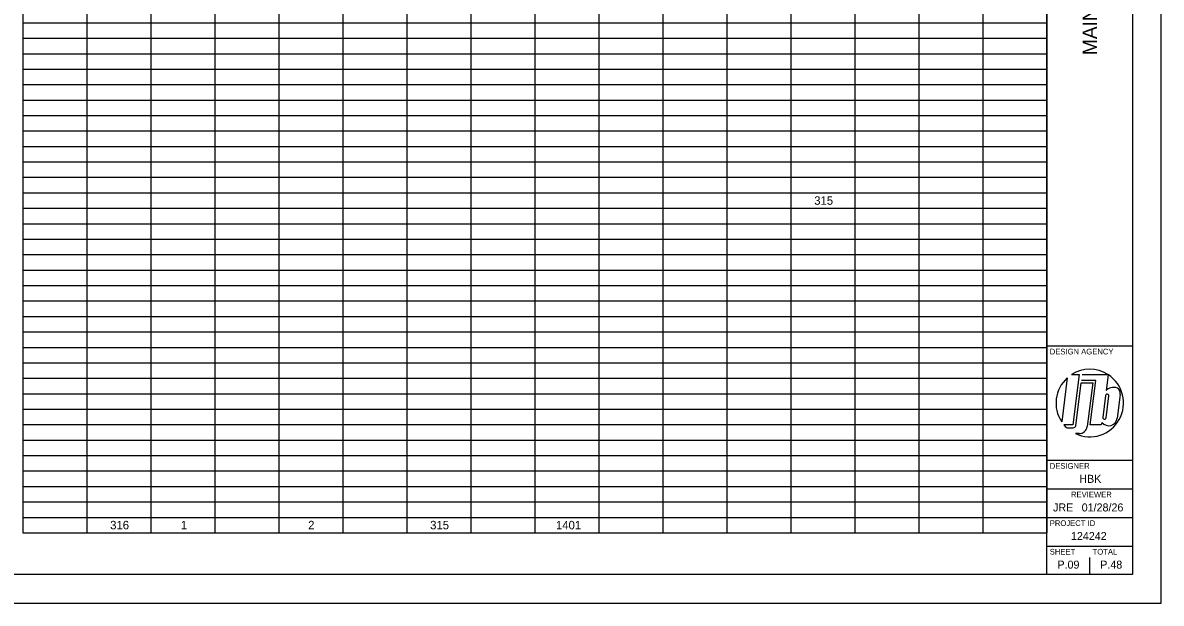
# Model space of a CAD drawing. Extents: x 0 to 34, y 0 to 22.
# Drawn here: x 14.09 to 34, y 0 to 10.15 of the extents above; entities that cross this region are included whole.
import ezdxf

# ---------------------------------------------------------------- set-up
doc = ezdxf.new("R2010")
doc.units = 0
for name, color, linetype in [('Default', 7, 'Continuous'), ('SH_Border', 7, 'Continuous'), ('SH_Cut_Line', 7, 'Continuous'), ('SH_Data', 7, 'Continuous')]:
    doc.layers.add(name, color=color, linetype=linetype)

msp = doc.modelspace()

# ---------------------------------------------------------------- linework, layer by layer
at = {"layer": 'Default'}
for p, q in [((14.086, 10.96), (14.086, 10.149)), ((15.206, 10.96), (15.206, 10.149)), ((16.325, 10.96), (16.325, 10.149)), ((17.445, 10.96), (17.445, 10.149)), ((18.565, 10.96), (18.565, 10.149)), ((19.684, 10.96), (19.684, 10.149)), ((20.804, 10.96), (20.804, 10.149)), ((21.923, 10.96), (21.923, 10.149)), ((23.043, 10.96), (23.043, 10.149)), ((24.163, 10.96), (24.163, 10.149)), ((25.282, 10.96), (25.282, 10.149)), ((26.402, 10.96), (26.402, 10.149)), ((27.522, 10.96), (27.522, 10.149)), ((28.641, 10.96), (28.641, 10.149)), ((29.761, 10.96), (29.761, 10.149)), ((30.88, 10.96), (30.88, 10.149)), ((32, 10.96), (32, 10.149)), ((14.086, 10.149), (15.206, 10.149)), ((14.086, 10.149), (14.086, 9.609)), ((15.206, 10.149), (16.325, 10.149)), ((15.206, 10.149), (15.206, 9.609)), ((16.325, 10.149), (24.163, 10.149)), ((16.325, 10.149), (16.325, 9.609)), ((17.445, 10.149), (17.445, 9.609)), ((18.565, 10.149), (18.565, 9.609)), ((19.684, 10.149), (19.684, 9.609)), ((20.804, 10.149), (20.804, 9.609)), ((21.923, 10.149), (21.923, 9.609)), ((23.043, 10.149), (23.043, 9.609)), ((24.163, 10.149), (25.282, 10.149)), ((24.163, 10.149), (24.163, 9.609)), ((25.282, 10.149), (27.522, 10.149)), ((25.282, 10.149), (25.282, 9.609)), ((26.402, 10.149), (26.402, 9.609)), ((27.522, 10.149), (30.88, 10.149)), ((27.522, 10.149), (27.522, 9.609)), ((28.641, 10.149), (28.641, 9.609)), ((29.761, 10.149), (29.761, 9.609)), ((30.88, 10.149), (32, 10.149)), ((30.88, 10.149), (30.88, 9.609)), ((32, 10.149), (32, 9.609)), ((14.086, 9.879), (15.206, 9.879)), ((15.206, 9.879), (16.325, 9.879)), ((16.325, 9.879), (24.163, 9.879)), ((24.163, 9.879), (25.282, 9.879)), ((25.282, 9.879), (27.522, 9.879)), ((27.522, 9.879), (30.88, 9.879)), ((30.88, 9.879), (32, 9.879)), ((14.086, 9.609), (15.206, 9.609)), ((14.086, 9.609), (14.086, 8.798)), ((15.206, 9.609), (16.325, 9.609)), ((15.206, 9.609), (15.206, 8.798)), ((16.325, 9.609), (24.163, 9.609)), ((16.325, 9.609), (16.325, 8.798)), ((17.445, 9.609), (17.445, 8.798)), ((18.565, 9.609), (18.565, 8.798)), ((19.684, 9.609), (19.684, 8.798)), ((20.804, 9.609), (20.804, 8.798)), ((21.923, 9.609), (21.923, 8.798)), ((23.043, 9.609), (23.043, 8.798)), ((24.163, 9.609), (25.282, 9.609)), ((24.163, 9.609), (24.163, 8.798)), ((25.282, 9.609), (27.522, 9.609)), ((25.282, 9.609), (25.282, 8.798)), ((26.402, 9.609), (26.402, 8.798)), ((27.522, 9.609), (30.88, 9.609)), ((27.522, 9.609), (27.522, 8.798)), ((28.641, 9.609), (28.641, 8.798)), ((29.761, 9.609), (29.761, 8.798)), ((30.88, 9.609), (32, 9.609)), ((30.88, 9.609), (30.88, 8.798)), ((32, 9.609), (32, 8.798)), ((14.086, 9.339), (15.206, 9.339)), ((15.206, 9.339), (16.325, 9.339)), ((16.325, 9.339), (24.163, 9.339)), ((24.163, 9.339), (25.282, 9.339)), ((25.282, 9.339), (27.522, 9.339)), ((27.522, 9.339), (30.88, 9.339)), ((30.88, 9.339), (32, 9.339)), ((14.086, 9.068), (15.206, 9.068)), ((15.206, 9.068), (16.325, 9.068)), ((16.325, 9.068), (24.163, 9.068)), ((24.163, 9.068), (25.282, 9.068)), ((25.282, 9.068), (27.522, 9.068)), ((27.522, 9.068), (30.88, 9.068)), ((30.88, 9.068), (32, 9.068)), ((14.086, 8.798), (15.206, 8.798)), ((14.086, 8.798), (14.086, 8.258)), ((15.206, 8.798), (16.325, 8.798)), ((15.206, 8.798), (15.206, 8.258)), ((16.325, 8.798), (24.163, 8.798)), ((16.325, 8.798), (16.325, 8.258)), ((17.445, 8.798), (17.445, 8.258)), ((18.565, 8.798), (18.565, 8.258)), ((19.684, 8.798), (19.684, 8.258)), ((20.804, 8.798), (20.804, 8.258)), ((21.923, 8.798), (21.923, 8.258)), ((23.043, 8.798), (23.043, 8.258)), ((24.163, 8.798), (25.282, 8.798)), ((24.163, 8.798), (24.163, 8.258)), ((25.282, 8.798), (27.522, 8.798)), ((25.282, 8.798), (25.282, 8.258)), ((26.402, 8.798), (26.402, 8.258)), ((27.522, 8.798), (30.88, 8.798)), ((27.522, 8.798), (27.522, 8.258)), ((28.641, 8.798), (28.641, 8.258)), ((29.761, 8.798), (29.761, 8.258)), ((30.88, 8.798), (32, 8.798)), ((30.88, 8.798), (30.88, 8.258)), ((32, 8.798), (32, 8.258)), ((14.086, 8.528), (15.206, 8.528)), ((15.206, 8.528), (16.325, 8.528)), ((16.325, 8.528), (24.163, 8.528)), ((24.163, 8.528), (25.282, 8.528)), ((25.282, 8.528), (27.522, 8.528)), ((27.522, 8.528), (30.88, 8.528)), ((30.88, 8.528), (32, 8.528)), ((14.086, 8.258), (15.206, 8.258)), ((14.086, 8.258), (14.086, 7.447)), ((15.206, 8.258), (16.325, 8.258)), ((15.206, 8.258), (15.206, 7.447)), ((16.325, 8.258), (24.163, 8.258)), ((16.325, 8.258), (16.325, 7.447)), ((17.445, 8.258), (17.445, 7.447)), ((18.565, 8.258), (18.565, 7.447)), ((19.684, 8.258), (19.684, 7.447)), ((20.804, 8.258), (20.804, 7.447)), ((21.923, 8.258), (21.923, 7.447)), ((23.043, 8.258), (23.043, 7.447)), ((24.163, 8.258), (25.282, 8.258)), ((24.163, 8.258), (24.163, 7.447)), ((25.282, 8.258), (27.522, 8.258)), ((25.282, 8.258), (25.282, 7.447)), ((26.402, 8.258), (26.402, 7.447)), ((27.522, 8.258), (30.88, 8.258)), ((27.522, 8.258), (27.522, 7.447)), ((28.641, 8.258), (28.641, 7.447)), ((29.761, 8.258), (29.761, 7.447)), ((30.88, 8.258), (32, 8.258)), ((30.88, 8.258), (30.88, 7.447)), ((32, 8.258), (32, 7.447)), ((14.086, 7.987), (15.206, 7.987)), ((15.206, 7.987), (16.325, 7.987)), ((16.325, 7.987), (24.163, 7.987)), ((24.163, 7.987), (25.282, 7.987)), ((25.282, 7.987), (27.522, 7.987)), ((27.522, 7.987), (30.88, 7.987)), ((30.88, 7.987), (32, 7.987)), ((14.086, 7.717), (15.206, 7.717)), ((15.206, 7.717), (16.325, 7.717)), ((16.325, 7.717), (24.163, 7.717)), ((24.163, 7.717), (25.282, 7.717)), ((25.282, 7.717), (27.522, 7.717)), ((27.522, 7.717), (30.88, 7.717)), ((30.88, 7.717), (32, 7.717)), ((14.086, 7.447), (15.206, 7.447)), ((14.086, 7.447), (14.086, 6.906)), ((15.206, 7.447), (16.325, 7.447)), ((15.206, 7.447), (15.206, 6.906)), ((16.325, 7.447), (24.163, 7.447)), ((16.325, 7.447), (16.325, 6.906)), ((17.445, 7.447), (17.445, 6.906)), ((18.565, 7.447), (18.565, 6.906)), ((19.684, 7.447), (19.684, 6.906)), ((20.804, 7.447), (20.804, 6.906)), ((21.923, 7.447), (21.923, 6.906)), ((23.043, 7.447), (23.043, 6.906)), ((24.163, 7.447), (25.282, 7.447)), ((24.163, 7.447), (24.163, 6.906)), ((25.282, 7.447), (27.522, 7.447)), ((25.282, 7.447), (25.282, 6.906)), ((26.402, 7.447), (26.402, 6.906)), ((27.522, 7.447), (30.88, 7.447)), ((27.522, 7.447), (27.522, 6.906)), ((28.641, 7.447), (28.641, 6.906)), ((29.761, 7.447), (29.761, 6.906)), ((30.88, 7.447), (32, 7.447)), ((30.88, 7.447), (30.88, 6.906)), ((32, 7.447), (32, 6.906)), ((14.086, 7.177), (15.206, 7.177)), ((15.206, 7.177), (16.325, 7.177)), ((16.325, 7.177), (24.163, 7.177)), ((24.163, 7.177), (25.282, 7.177)), ((25.282, 7.177), (27.522, 7.177)), ((27.522, 7.177), (30.88, 7.177)), ((30.88, 7.177), (32, 7.177)), ((14.086, 6.906), (15.206, 6.906)), ((14.086, 6.906), (14.086, 1.231)), ((15.206, 6.906), (16.325, 6.906)), ((15.206, 6.906), (15.206, 1.231)), ((16.325, 6.906), (24.163, 6.906)), ((16.325, 6.906), (16.325, 1.231)), ((17.445, 6.906), (17.445, 1.231)), ((18.565, 6.906), (18.565, 1.231)), ((19.684, 6.906), (19.684, 1.231)), ((20.804, 6.906), (20.804, 1.231)), ((21.923, 6.906), (21.923, 1.231)), ((23.043, 6.906), (23.043, 1.231)), ((24.163, 6.906), (25.282, 6.906)), ((24.163, 6.906), (24.163, 1.231)), ((25.282, 6.906), (27.522, 6.906)), ((25.282, 6.906), (25.282, 1.231)), ((26.402, 6.906), (26.402, 1.231)), ((27.522, 6.906), (30.88, 6.906)), ((27.522, 6.906), (27.522, 1.231)), ((28.641, 6.906), (28.641, 1.231)), ((29.761, 6.906), (29.761, 1.231)), ((30.88, 6.906), (32, 6.906)), ((30.88, 6.906), (30.88, 1.231)), ((32, 6.906), (32, 1.231)), ((14.086, 6.636), (15.206, 6.636)), ((15.206, 6.636), (16.325, 6.636)), ((16.325, 6.636), (24.163, 6.636)), ((24.163, 6.636), (25.282, 6.636)), ((25.282, 6.636), (27.522, 6.636)), ((27.522, 6.636), (30.88, 6.636)), ((30.88, 6.636), (32, 6.636)), ((14.086, 6.366), (15.206, 6.366)), ((15.206, 6.366), (16.325, 6.366)), ((16.325, 6.366), (24.163, 6.366)), ((24.163, 6.366), (25.282, 6.366)), ((25.282, 6.366), (27.522, 6.366)), ((27.522, 6.366), (30.88, 6.366)), ((30.88, 6.366), (32, 6.366)), ((14.086, 6.096), (15.206, 6.096)), ((15.206, 6.096), (16.325, 6.096)), ((16.325, 6.096), (24.163, 6.096)), ((24.163, 6.096), (25.282, 6.096)), ((25.282, 6.096), (27.522, 6.096)), ((27.522, 6.096), (30.88, 6.096)), ((30.88, 6.096), (32, 6.096)), ((14.086, 5.825), (15.206, 5.825)), ((15.206, 5.825), (16.325, 5.825)), ((16.325, 5.825), (24.163, 5.825)), ((24.163, 5.825), (25.282, 5.825)), ((25.282, 5.825), (27.522, 5.825)), ((27.522, 5.825), (30.88, 5.825)), ((30.88, 5.825), (32, 5.825)), ((14.086, 5.555), (15.206, 5.555)), ((15.206, 5.555), (16.325, 5.555)), ((16.325, 5.555), (24.163, 5.555)), ((24.163, 5.555), (25.282, 5.555)), ((25.282, 5.555), (27.522, 5.555)), ((27.522, 5.555), (30.88, 5.555)), ((30.88, 5.555), (32, 5.555)), ((14.086, 5.285), (15.206, 5.285)), ((15.206, 5.285), (16.325, 5.285)), ((16.325, 5.285), (24.163, 5.285)), ((24.163, 5.285), (25.282, 5.285)), ((25.282, 5.285), (27.522, 5.285)), ((27.522, 5.285), (30.88, 5.285)), ((30.88, 5.285), (32, 5.285)), ((14.086, 5.015), (15.206, 5.015)), ((15.206, 5.015), (16.325, 5.015)), ((16.325, 5.015), (24.163, 5.015)), ((24.163, 5.015), (25.282, 5.015)), ((25.282, 5.015), (27.522, 5.015)), ((27.522, 5.015), (30.88, 5.015)), ((30.88, 5.015), (32, 5.015)), ((14.086, 4.744), (15.206, 4.744)), ((15.206, 4.744), (16.325, 4.744)), ((16.325, 4.744), (24.163, 4.744)), ((24.163, 4.744), (25.282, 4.744)), ((25.282, 4.744), (27.522, 4.744)), ((27.522, 4.744), (30.88, 4.744)), ((30.88, 4.744), (32, 4.744)), ((14.086, 4.474), (15.206, 4.474)), ((15.206, 4.474), (16.325, 4.474)), ((16.325, 4.474), (24.163, 4.474)), ((24.163, 4.474), (25.282, 4.474)), ((25.282, 4.474), (27.522, 4.474)), ((27.522, 4.474), (30.88, 4.474)), ((30.88, 4.474), (32, 4.474)), ((14.086, 4.204), (15.206, 4.204)), ((15.206, 4.204), (16.325, 4.204)), ((16.325, 4.204), (24.163, 4.204)), ((24.163, 4.204), (25.282, 4.204)), ((25.282, 4.204), (27.522, 4.204)), ((27.522, 4.204), (30.88, 4.204)), ((30.88, 4.204), (32, 4.204)), ((14.086, 3.934), (15.206, 3.934)), ((15.206, 3.934), (16.325, 3.934)), ((16.325, 3.934), (24.163, 3.934)), ((24.163, 3.934), (25.282, 3.934)), ((25.282, 3.934), (27.522, 3.934)), ((27.522, 3.934), (30.88, 3.934)), ((30.88, 3.934), (32, 3.934)), ((14.086, 3.663), (15.206, 3.663)), ((15.206, 3.663), (16.325, 3.663)), ((16.325, 3.663), (24.163, 3.663)), ((24.163, 3.663), (25.282, 3.663)), ((25.282, 3.663), (27.522, 3.663)), ((27.522, 3.663), (30.88, 3.663)), ((30.88, 3.663), (32, 3.663)), ((14.086, 3.393), (15.206, 3.393)), ((15.206, 3.393), (16.325, 3.393)), ((16.325, 3.393), (24.163, 3.393)), ((24.163, 3.393), (25.282, 3.393)), ((25.282, 3.393), (27.522, 3.393)), ((27.522, 3.393), (30.88, 3.393)), ((30.88, 3.393), (32, 3.393)), ((14.086, 3.123), (15.206, 3.123)), ((15.206, 3.123), (16.325, 3.123)), ((16.325, 3.123), (24.163, 3.123)), ((24.163, 3.123), (25.282, 3.123)), ((25.282, 3.123), (27.522, 3.123)), ((27.522, 3.123), (30.88, 3.123)), ((30.88, 3.123), (32, 3.123)), ((14.086, 2.853), (15.206, 2.853)), ((15.206, 2.853), (16.325, 2.853)), ((16.325, 2.853), (24.163, 2.853)), ((24.163, 2.853), (25.282, 2.853)), ((25.282, 2.853), (27.522, 2.853)), ((27.522, 2.853), (30.88, 2.853)), ((30.88, 2.853), (32, 2.853)), ((14.086, 2.582), (15.206, 2.582)), ((15.206, 2.582), (16.325, 2.582)), ((16.325, 2.582), (24.163, 2.582)), ((24.163, 2.582), (25.282, 2.582)), ((25.282, 2.582), (27.522, 2.582)), ((27.522, 2.582), (30.88, 2.582)), ((30.88, 2.582), (32, 2.582)), ((14.086, 2.312), (15.206, 2.312)), ((15.206, 2.312), (16.325, 2.312)), ((16.325, 2.312), (24.163, 2.312)), ((24.163, 2.312), (25.282, 2.312)), ((25.282, 2.312), (27.522, 2.312)), ((27.522, 2.312), (30.88, 2.312)), ((30.88, 2.312), (32, 2.312)), ((14.086, 2.042), (15.206, 2.042)), ((15.206, 2.042), (16.325, 2.042)), ((16.325, 2.042), (24.163, 2.042)), ((24.163, 2.042), (25.282, 2.042)), ((25.282, 2.042), (27.522, 2.042)), ((27.522, 2.042), (30.88, 2.042)), ((30.88, 2.042), (32, 2.042)), ((14.086, 1.772), (15.206, 1.772)), ((15.206, 1.772), (16.325, 1.772)), ((16.325, 1.772), (24.163, 1.772)), ((24.163, 1.772), (25.282, 1.772)), ((25.282, 1.772), (27.522, 1.772)), ((27.522, 1.772), (30.88, 1.772)), ((30.88, 1.772), (32, 1.772)), ((14.086, 1.501), (15.206, 1.501)), ((15.206, 1.501), (16.325, 1.501)), ((16.325, 1.501), (24.163, 1.501)), ((24.163, 1.501), (25.282, 1.501)), ((25.282, 1.501), (27.522, 1.501)), ((27.522, 1.501), (30.88, 1.501)), ((30.88, 1.501), (32, 1.501)), ((14.086, 1.231), (15.206, 1.231)), ((15.206, 1.231), (16.325, 1.231)), ((16.325, 1.231), (24.163, 1.231)), ((24.163, 1.231), (25.282, 1.231)), ((25.282, 1.231), (27.522, 1.231)), ((27.522, 1.231), (30.88, 1.231)), ((30.88, 1.231), (32, 1.231))]:
    msp.add_line(p, q, dxfattribs=at)
at = {"layer": 'SH_Border'}
for p, q in [((32, 0.5), (32, 21.5)), ((32, 4.5), (33.5, 4.5)), ((32, 2.5), (33.5, 2.5)), ((32, 2), (33.5, 2)), ((32, 1.5), (33.5, 1.5)), ((32, 1), (33.5, 1))]:
    msp.add_line(p, q, dxfattribs=at)
msp.add_lwpolyline([(1.5, 21.5), (33.5, 21.5), (33.5, 0.5), (1.5, 0.5)], close=True, dxfattribs=at)
at = {"layer": 'SH_Cut_Line'}
msp.add_lwpolyline([(0, 0), (34, 0), (34, 22), (0, 22)], close=True, dxfattribs=at)
at = {"layer": 'SH_Data'}
for p, q in [((32.432, 3.998), (32.567, 3.998)), ((32.567, 3.998), (32.456, 3.118)), ((32.617, 4), (33.065, 4)), ((33.07, 3.996), (33.035, 3.72)), ((32.356, 3.94), (32.259, 3.171)), ((32.504, 3.104), (32.599, 3.855)), ((32.599, 3.855), (32.801, 3.855)), ((32.856, 3.896), (32.604, 3.896)), ((32.801, 3.855), (32.704, 3.089)), ((32.758, 3.118), (32.856, 3.896)), ((33.024, 3.631), (32.976, 3.25)), ((33.036, 3.243), (33.084, 3.624)), ((33.283, 3.648), (33.231, 3.237)), ((32.75, 3.5), (32.75, 3.5)), ((32.456, 3.118), (32.299, 3.118)), ((32.347, 3.068), (32.462, 3.068)), ((32.947, 3.118), (32.758, 3.118)), ((32.964, 3.161), (32.947, 3.118)), ((32.564, 2.966), (32.498, 2.966)), ((32.75, 0.5), (32.75, 0.8)), ((32.375, 0.675), (32.375, 0.675))]:
    msp.add_line(p, q, dxfattribs=at)
for centre, radius, start, end in [((32.75, 3.5), 0.591, 57.726, 122.5688), ((32.75, 3.5), 0.591, 244.7646, 57.1575), ((32.75, 3.5), 0.591, 131.8253, 213.7822), ((33.054, 3.628), 0.0301, 352.3298, 173.2777), ((33.17, 3.586), 0.19, 105.9444, 135.0487), ((33.164, 3.6), 0.175, 66.6782, 105.4185), ((33.177, 3.669), 0.108, 349.2072, 58.7163), ((33.081, 3.255), 0.151, 218.6264, 353.0883), ((33.006, 3.246), 0.0301, 172.3335, 353.274), ((32.75, 3.5), 0.591, 220.2786, 227.0158), ((32.462, 3.109), 0.0417, 270, 352.8038), ((32.564, 3.106), 0.141, 270, 352.8038)]:
    msp.add_arc(centre, radius, start, end, dxfattribs=at)

# ---------------------------------------------------------------- texts
at = {"layer": 'Default'}
for s, p in [('315', (27.93, 6.967)), ('316', (15.615, 1.292)), ('1', (16.851, 1.292)), ('2', (19.078, 1.292)), ('315', (21.212, 1.292)), ('1401', (23.413, 1.292))]:
    msp.add_text(s, height=0.148, dxfattribs=at).set_placement(p)
at = {"layer": 'SH_Data'}
msp.add_text('MAINTENANCE OF TRAFFIC SUBSUMMARY', height=0.25, rotation=90, dxfattribs=at).set_placement((32.875, 9.584))
for s, height, p in [('DESIGN AGENCY', 0.1, (32.05, 4.35)), ('DESIGNER', 0.1, (32.05, 2.35)), ('HBK', 0.14, (32.567, 2.105)), ('REVIEWER', 0.1, (32.422, 1.85)), ('JRE', 0.14, (32.107, 1.605)), ('01/28/26', 0.14, (32.609, 1.605)), ('PROJECT ID', 0.1, (32.05, 1.35)), ('124242', 0.14, (32.421, 1.105)), ('SHEET', 0.1, (32.05, 0.85)), ('TOTAL', 0.1, (32.8, 0.85)), ('P.09', 0.14, (32.184, 0.605)), ('P.48', 0.14, (32.933, 0.605))]:
    msp.add_text(s, height=height, dxfattribs=at).set_placement(p)

doc.saveas('drawing.dxf')
